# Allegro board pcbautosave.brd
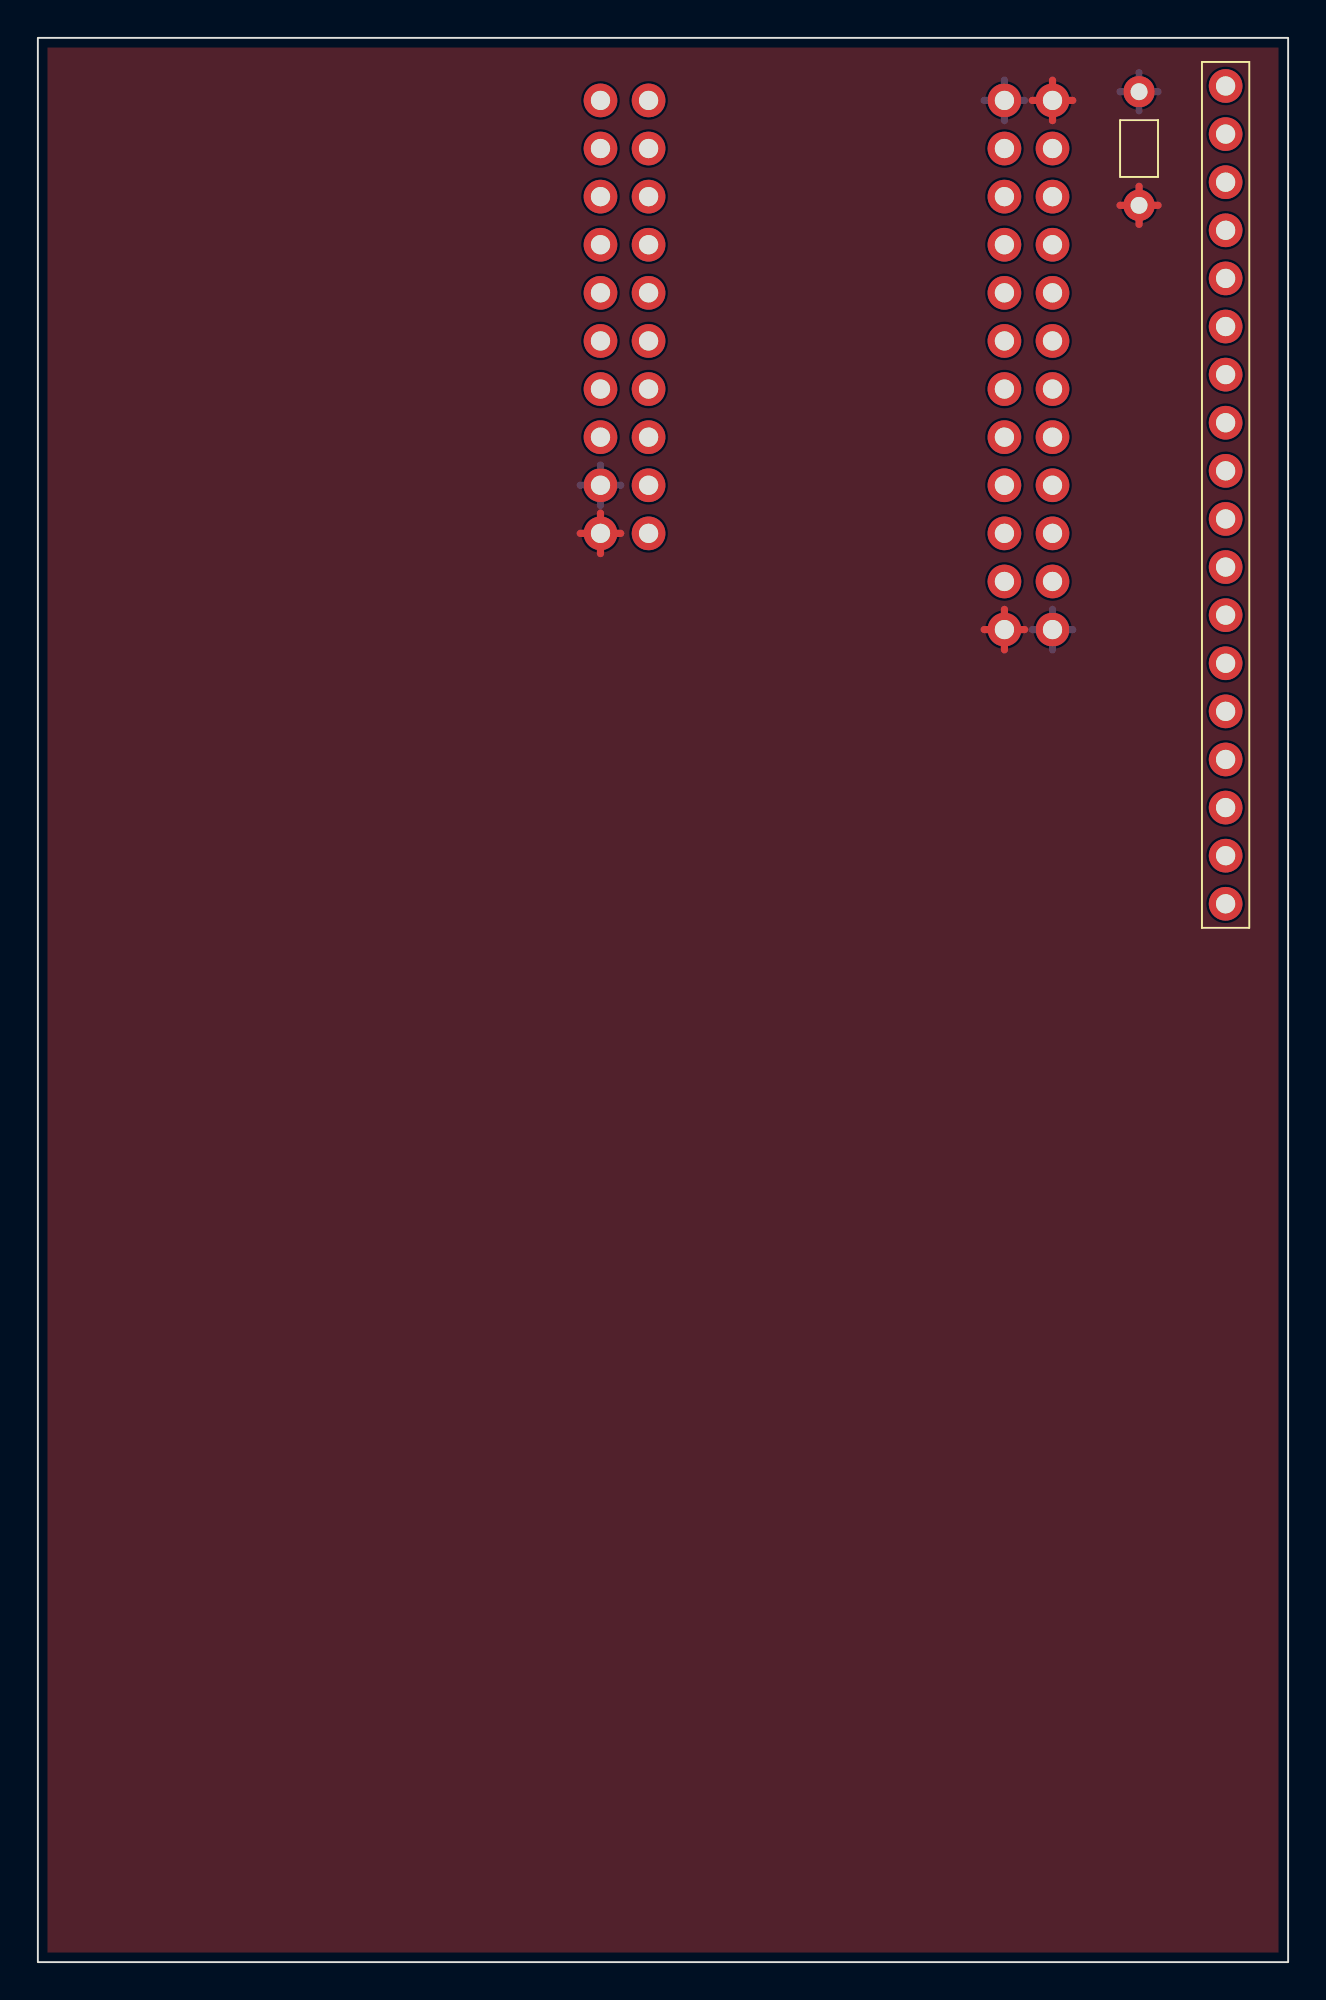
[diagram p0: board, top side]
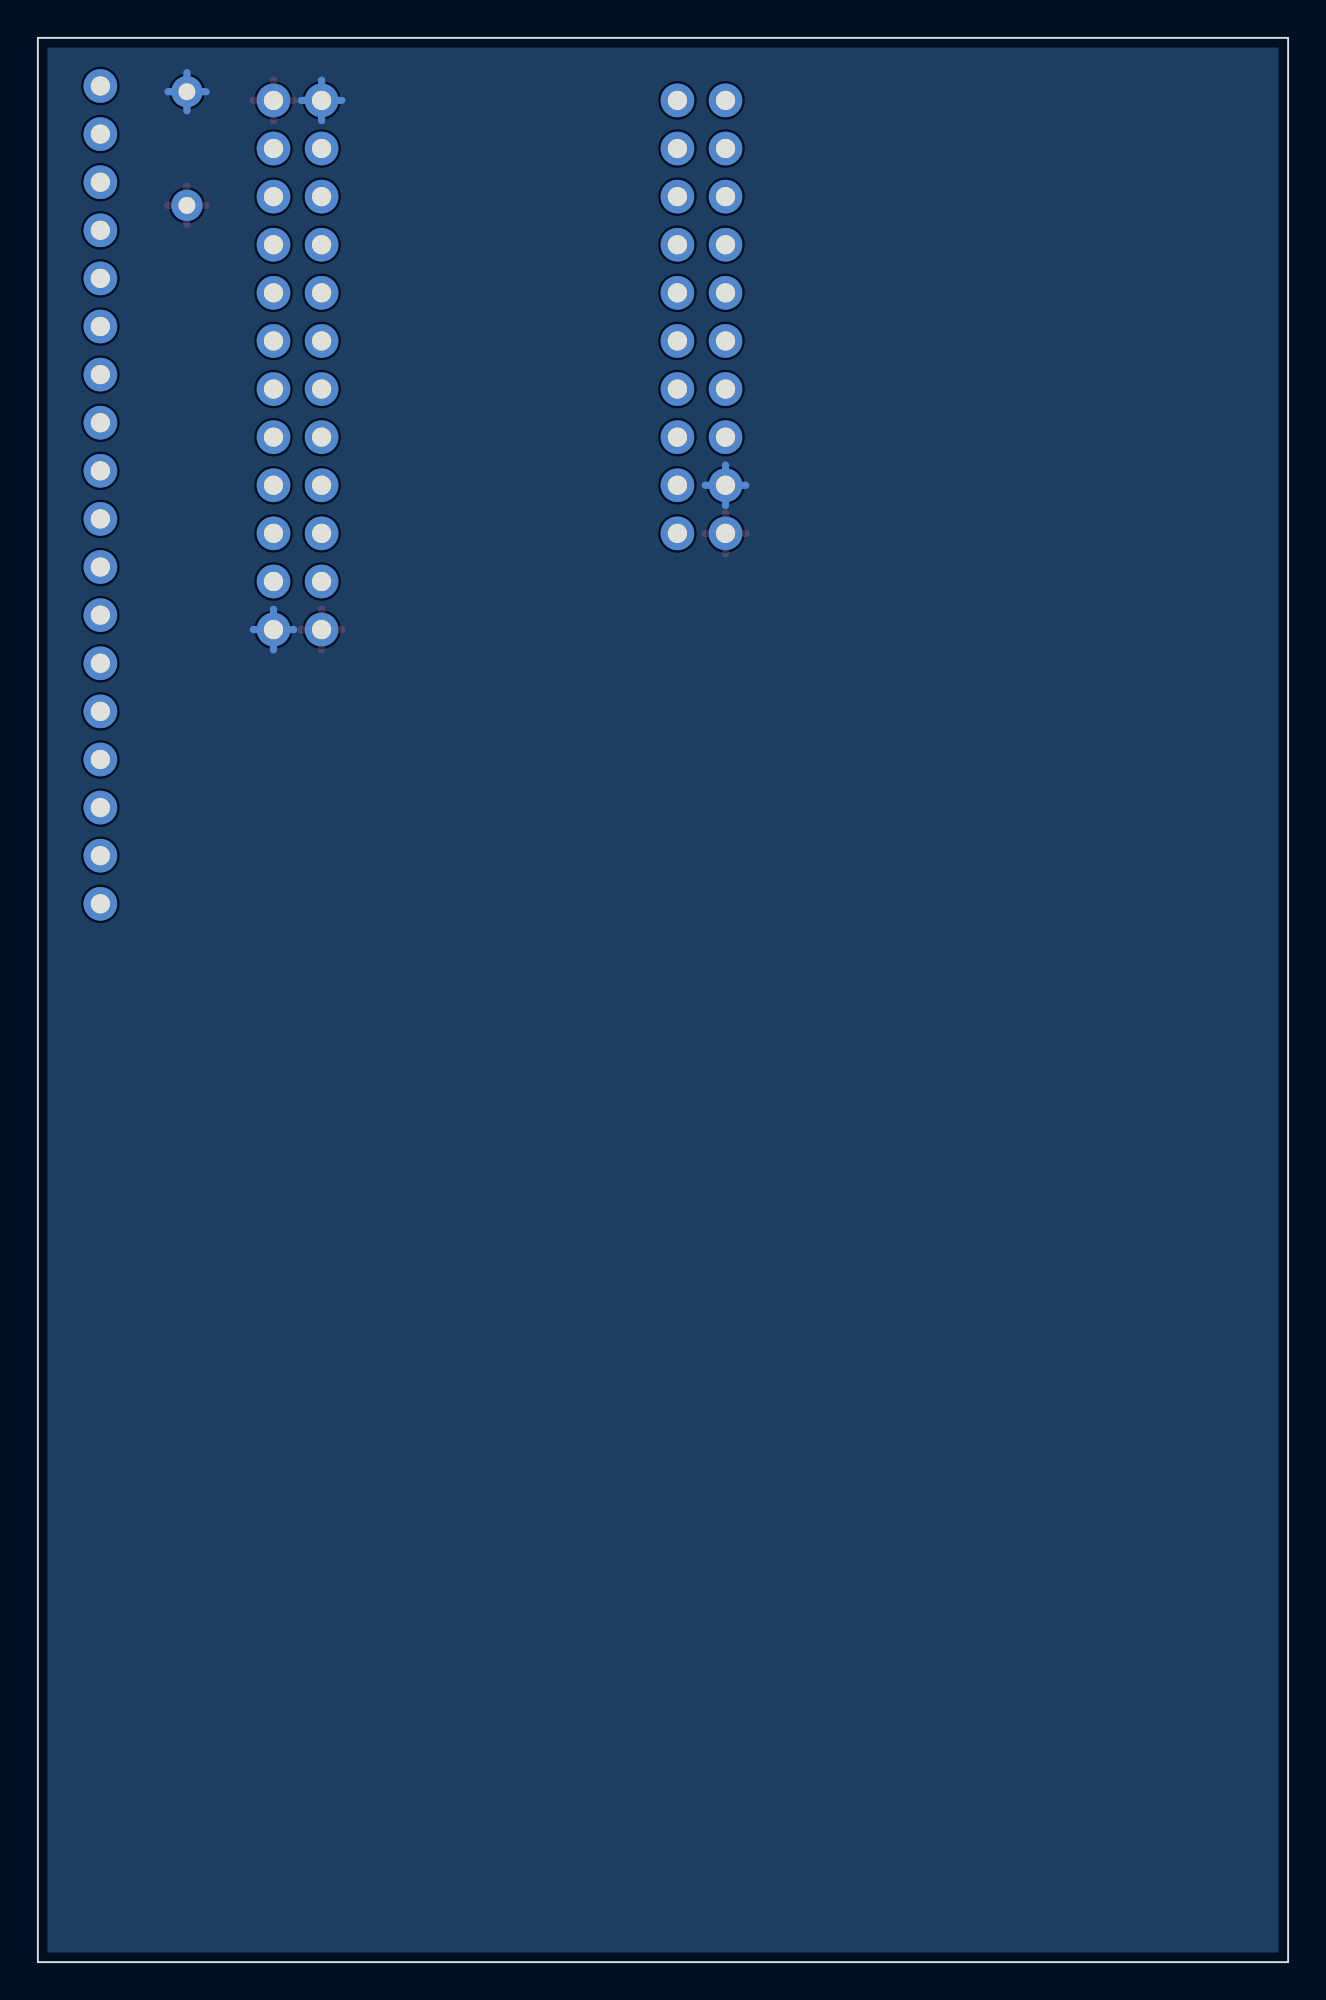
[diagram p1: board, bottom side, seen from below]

Outline 66.04 x 101.6 mm; copper layers: TOP, BOTTOM. Coordinates in mm from the lower left corner of the outline.
Outline path: rectangle 0,0 66.04,101.6

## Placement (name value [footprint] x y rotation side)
C5  0.1 uF 50V  [CAP1]  58.17 95.76 90 top
J2  HEADER 18  [HEADER_18]  62.74 77.47 0 top
U3  PSoC4BLE  [PSOC4BLE]  29.72 98.3 0 top

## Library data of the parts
C5 = CAP NP
J2 = HEADER 18
U3 = PSoC4BLE_0

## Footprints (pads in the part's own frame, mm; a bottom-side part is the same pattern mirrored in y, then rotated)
CAP1
  round 1.651 hole 0.889: 1(-3,0) 2(3,0)
HEADER_18
  round 1.778 hole 1.016: 1(0,21.59) 2(0,19.05) 3(0,16.51) 4(0,13.97) 5(0,11.43) 6(0,8.89) 7(0,6.35) 8(0,3.81) 9(0,1.27) 10(0,-1.27) 11(0,-3.81) 12(0,-6.35) 13(0,-8.89) 14(0,-11.43) 15(0,-13.97) 16(0,-16.51) 17(0,-19.05) 18(0,-21.59)
PSOC4BLE
  round 1.778 hole 1.016: 1(2.54,-22.86) 2(0,-22.86) 3(2.54,-20.32) 4(0,-20.32) 5(2.54,-17.78) 6(0,-17.78) 7(2.54,-15.24) 8(0,-15.24) 9(2.54,-12.7) 10(0,-12.7) 11(2.54,-10.16) 12(0,-10.16) 13(2.54,-7.62) 14(0,-7.62) 15(2.54,-5.08) 16(0,-5.08) 17(2.54,-2.54) 18(0,-2.54) 19(2.54,0) 20(0,0) 21(21.336,0) 22(23.876,0) 23(21.336,-2.54) 24(23.876,-2.54) 25(21.336,-5.08) 26(23.876,-5.08) 27(21.336,-7.62) 28(23.876,-7.62) 29(21.336,-10.16) 30(23.876,-10.16) 31(21.336,-12.7) 32(23.876,-12.7) 33(21.336,-15.24) 34(23.876,-15.24) 35(21.336,-17.78) 36(23.876,-17.78) 37(21.336,-20.32) 38(23.876,-20.32) 39(21.336,-22.86) 40(23.876,-22.86) 41(21.336,-25.4) 42(23.876,-25.4) 43(21.336,-27.94) 44(23.876,-27.94)

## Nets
GND: C5.2 U3.4(GND1) U3.21(GND2) U3.44(GND3)
+5 V: C5.1 U3.2(VDDD) U3.22(VDDA) U3.43(VDDR)
RXD: U3.11(P1.1)
TXD: U3.12(P1.2)
N56918: U3.15(P0.4)
N57246: J2.18 U3.42(P2.1)
N57250: J2.17 U3.41(P2.0)
N57254: J2.16 U3.40(P2.3)
N57258: J2.15 U3.39(P2.2)
N57262: J2.14 U3.38(P2.5)
N57266: J2.13 U3.37(P2.4)
N57270: J2.12 U3.36(P2.7)
N57274: J2.11 U3.35(P2.6)
N57278: J2.10 U3.34(P5.0)
N57282: J2.9 U3.33(P4.1)
N57286: J2.8 U3.32(P5.1)
N57290: J2.7 U3.31(P4.0)
N57294: J2.6 U3.30(P3.1)
N57298: J2.5 U3.29(P3.0)
N57318: J2.4 U3.28(P3.3)
N57322: J2.3 U3.27(P3.2)
N57332: J2.2 U3.26(P3.5)
N57336: J2.1 U3.25(P3.4)

Pads without a net: U3 1 3 5 6 7 8 9 10 13 14 16 17 18 19 20 23 24

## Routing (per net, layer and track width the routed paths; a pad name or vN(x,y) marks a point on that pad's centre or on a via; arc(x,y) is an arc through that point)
GND: length 16.8
  BOTTOM w0.381: C5.2 58.17,99.76 ; C5.2 57.16,98.76 ; C5.2 58.17,97.75 ; C5.2 59.17,98.76 ; U3.4 30.79,77.98 ; U3.4 28.65,77.98 ; U3.4 29.72,79.05 ; U3.4 29.72,76.91 ; U3.21 52.12,98.3 ; U3.21 51.05,99.37 ; U3.21 49.99,98.3 ; U3.21 51.05,97.23 ; U3.44 54.66,70.36 ; U3.44 52.53,70.36 ; U3.44 53.59,71.43 ; U3.44 53.59,69.29
+5 V: length 16.8
  TOP w0.381: U3.43 52.12,70.36 ; U3.43 51.05,69.29 ; U3.43 51.05,71.43 ; U3.43 49.99,70.36 ; 58.17,91.75 C5.1 ; C5.1 57.16,92.76 ; C5.1 58.17,93.76 ; C5.1 59.17,92.76 ; 29.72,74.37 U3.2 ; U3.2 29.72,76.51 ; U3.2 28.65,75.44 ; U3.2 30.79,75.44 ; 53.59,97.23 U3.22 ; U3.22 54.66,98.3 ; U3.22 53.59,99.37 ; U3.22 52.53,98.3

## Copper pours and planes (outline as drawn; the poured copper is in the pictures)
GND on BOTTOM: 0.51,0.51 0.51,101.09 65.53,101.09 65.53,0.51
+5 V on TOP: 0.51,0.51 0.51,101.09 65.53,101.09 65.53,0.51
